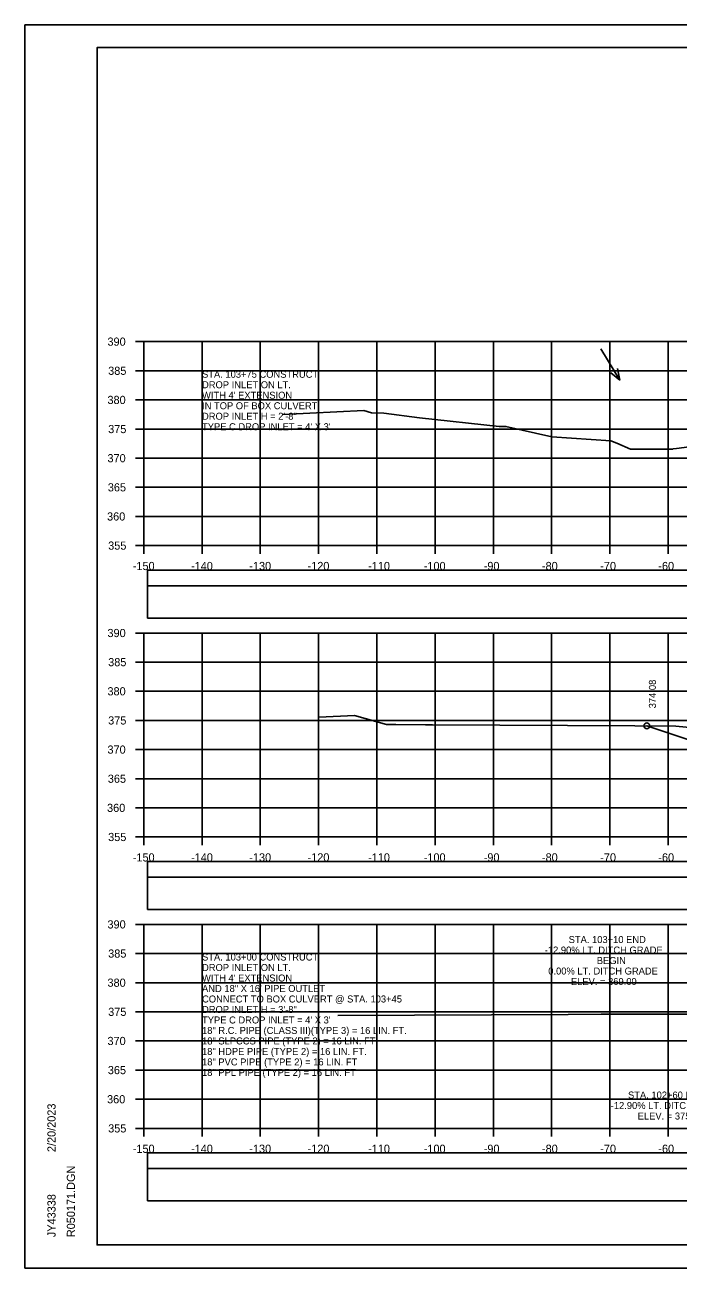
# Model space of a CAD drawing. Extents: x -37291014 to -37290680, y -936053 to -933067.
# Drawn here: x -37291013.5 to -37290901.4, y -935413.3 to -935200 of the extents above; entities that cross this region are included whole.
import ezdxf

# ---------------------------------------------------------------- set-up
doc = ezdxf.new("R2010")
doc.units = 0
for name, color, linetype in [('Default', 7, 'Continuous'), ('R_Axis', 7, 'Continuous'), ('R_Axis Annot', 7, 'Continuous'), ('R_Border', 7, 'Continuous'), ('R_Contours', 7, 'Continuous'), ('R_Exist Surface', 7, 'Continuous'), ('R_Fin Surface', 7, 'Continuous'), ('R_Grid', 7, 'Continuous'), ('R_No Plot', 7, 'Continuous'), ('R_Water Annot', 7, 'Continuous'), ('R_Xsect Elev', 7, 'Continuous')]:
    doc.layers.add(name, color=color, linetype=linetype)

msp = doc.modelspace()

# ---------------------------------------------------------------- linework, layer by layer
at = {"layer": 'Default'}
for points in [[(-37290992.48, -935296.22), (-37290693.72, -935296.22), (-37290693.72, -935293.51), (-37290992.48, -935293.51)], [(-37290992.48, -935301.74), (-37290693.72, -935301.74), (-37290693.72, -935296.22), (-37290992.48, -935296.22)], [(-37290992.48, -935346.22), (-37290693.72, -935346.22), (-37290693.72, -935343.51), (-37290992.48, -935343.51)], [(-37290992.48, -935351.74), (-37290693.72, -935351.74), (-37290693.72, -935346.22), (-37290992.48, -935346.22)], [(-37290992.48, -935396.22), (-37290693.72, -935396.22), (-37290693.72, -935393.51), (-37290992.48, -935393.51)], [(-37290992.48, -935401.74), (-37290693.72, -935401.74), (-37290693.72, -935396.22), (-37290992.48, -935396.22)]]:
    msp.add_lwpolyline(points, close=True, dxfattribs=at)
at = {"layer": 'R_Axis'}
for p, q in [((-37290994.5, -935254.31), (-37290993.1, -935254.31)), ((-37290993.1, -935289.31), (-37290993.1, -935254.31)), ((-37290994.5, -935259.31), (-37290993.1, -935259.31)), ((-37290994.5, -935264.31), (-37290993.1, -935264.31)), ((-37290994.5, -935269.31), (-37290993.1, -935269.31)), ((-37290994.5, -935274.31), (-37290993.1, -935274.31)), ((-37290994.5, -935279.31), (-37290993.1, -935279.31)), ((-37290994.5, -935284.31), (-37290993.1, -935284.31)), ((-37290994.5, -935289.31), (-37290993.1, -935289.31)), ((-37290993.1, -935289.31), (-37290693.1, -935289.31)), ((-37290993.1, -935290.71), (-37290993.1, -935289.31)), ((-37290983.1, -935290.71), (-37290983.1, -935289.31)), ((-37290973.1, -935290.71), (-37290973.1, -935289.31)), ((-37290963.1, -935290.71), (-37290963.1, -935289.31)), ((-37290953.1, -935290.71), (-37290953.1, -935289.31)), ((-37290943.1, -935290.71), (-37290943.1, -935289.31)), ((-37290933.1, -935290.71), (-37290933.1, -935289.31)), ((-37290923.1, -935290.71), (-37290923.1, -935289.31)), ((-37290913.1, -935290.71), (-37290913.1, -935289.31)), ((-37290903.1, -935290.71), (-37290903.1, -935289.31)), ((-37290994.5, -935304.31), (-37290993.1, -935304.31)), ((-37290993.1, -935339.31), (-37290993.1, -935304.31)), ((-37290994.5, -935309.31), (-37290993.1, -935309.31)), ((-37290994.5, -935314.31), (-37290993.1, -935314.31)), ((-37290994.5, -935319.31), (-37290993.1, -935319.31)), ((-37290994.5, -935324.31), (-37290993.1, -935324.31)), ((-37290994.5, -935329.31), (-37290993.1, -935329.31)), ((-37290994.5, -935334.31), (-37290993.1, -935334.31)), ((-37290994.5, -935339.31), (-37290993.1, -935339.31)), ((-37290993.1, -935339.31), (-37290693.1, -935339.31)), ((-37290993.1, -935340.71), (-37290993.1, -935339.31)), ((-37290983.1, -935340.71), (-37290983.1, -935339.31)), ((-37290973.1, -935340.71), (-37290973.1, -935339.31)), ((-37290963.1, -935340.71), (-37290963.1, -935339.31)), ((-37290953.1, -935340.71), (-37290953.1, -935339.31)), ((-37290943.1, -935340.71), (-37290943.1, -935339.31)), ((-37290933.1, -935340.71), (-37290933.1, -935339.31)), ((-37290923.1, -935340.71), (-37290923.1, -935339.31)), ((-37290913.1, -935340.71), (-37290913.1, -935339.31)), ((-37290903.1, -935340.71), (-37290903.1, -935339.31)), ((-37290994.5, -935354.31), (-37290993.1, -935354.31)), ((-37290993.1, -935389.31), (-37290993.1, -935354.31)), ((-37290994.5, -935359.31), (-37290993.1, -935359.31)), ((-37290994.5, -935364.31), (-37290993.1, -935364.31)), ((-37290994.5, -935369.31), (-37290993.1, -935369.31)), ((-37290994.5, -935374.31), (-37290993.1, -935374.31)), ((-37290994.5, -935379.31), (-37290993.1, -935379.31)), ((-37290994.5, -935384.31), (-37290993.1, -935384.31)), ((-37290994.5, -935389.31), (-37290993.1, -935389.31)), ((-37290993.1, -935389.31), (-37290693.1, -935389.31)), ((-37290993.1, -935390.71), (-37290993.1, -935389.31)), ((-37290983.1, -935390.71), (-37290983.1, -935389.31)), ((-37290973.1, -935390.71), (-37290973.1, -935389.31)), ((-37290963.1, -935390.71), (-37290963.1, -935389.31)), ((-37290953.1, -935390.71), (-37290953.1, -935389.31)), ((-37290943.1, -935390.71), (-37290943.1, -935389.31)), ((-37290933.1, -935390.71), (-37290933.1, -935389.31)), ((-37290923.1, -935390.71), (-37290923.1, -935389.31)), ((-37290913.1, -935390.71), (-37290913.1, -935389.31)), ((-37290903.1, -935390.71), (-37290903.1, -935389.31))]:
    msp.add_line(p, q, dxfattribs=at)
at = {"layer": 'R_Border'}
for p, q in [((-37291001.1, -935203.85), (-37290684.92, -935203.85)), ((-37291001.1, -935409.31), (-37291001.1, -935203.85)), ((-37291001.1, -935409.31), (-37291001.1, -935409.31)), ((-37290684.92, -935409.31), (-37291001.1, -935409.31))]:
    msp.add_line(p, q, dxfattribs=at)
at = {"layer": 'R_Contours'}
for points in [[(-37290883.54, -935322.53), (-37290886.6, -935321.98), (-37290887.07, -935321.81), (-37290896.49, -935320.81), (-37290901.79, -935320.28), (-37290906.76, -935320.23)], [(-37290906.76, -935320.23), (-37290891.52, -935325.31), (-37290883.3, -935322.57)]]:
    msp.add_lwpolyline(points, dxfattribs=at)
at = {"layer": 'R_Exist Surface'}
for points in [[(-37290969.25, -935266.79), (-37290955.32, -935266.15), (-37290954.01, -935266.51), (-37290951.92, -935266.59), (-37290945.77, -935267.37), (-37290932.12, -935268.87), (-37290930.96, -935268.85), (-37290923.05, -935270.62), (-37290912.93, -935271.35), (-37290911.92, -935271.75), (-37290909.54, -935272.77), (-37290907.92, -935272.77), (-37290902.28, -935272.74), (-37290902.23, -935272.73), (-37290901.68, -935272.65), (-37290897.77, -935272.12)], [(-37290962.98, -935318.74), (-37290956.91, -935318.47), (-37290951.43, -935319.98), (-37290949.84, -935320), (-37290944.77, -935320.04), (-37290943.53, -935320.04), (-37290908.82, -935320.21), (-37290901.79, -935320.28), (-37290896.49, -935320.81)], [(-37290959.82, -935369.94), (-37290920.28, -935369.77), (-37290914.61, -935369.74), (-37290913.95, -935369.74), (-37290875.06, -935369.72)]]:
    msp.add_lwpolyline(points, dxfattribs=at)
at = {"layer": 'R_Fin Surface'}
msp.add_lwpolyline([(-37290906.76, -935320.23), (-37290891.52, -935325.31)], dxfattribs=at)
at = {"layer": 'R_Grid'}
for p, q in [((-37290993.1, -935254.31), (-37290693.1, -935254.31)), ((-37290993.1, -935289.31), (-37290993.1, -935254.31)), ((-37290983.1, -935289.31), (-37290983.1, -935254.31)), ((-37290973.1, -935289.31), (-37290973.1, -935254.31)), ((-37290963.1, -935289.31), (-37290963.1, -935254.31)), ((-37290953.1, -935289.31), (-37290953.1, -935254.31)), ((-37290943.1, -935289.31), (-37290943.1, -935254.31)), ((-37290933.1, -935289.31), (-37290933.1, -935254.31)), ((-37290923.1, -935289.31), (-37290923.1, -935254.31)), ((-37290913.1, -935289.31), (-37290913.1, -935254.31)), ((-37290903.1, -935289.31), (-37290903.1, -935254.31)), ((-37290993.1, -935259.31), (-37290693.1, -935259.31)), ((-37290993.1, -935264.31), (-37290693.1, -935264.31)), ((-37290993.1, -935269.31), (-37290693.1, -935269.31)), ((-37290993.1, -935274.31), (-37290693.1, -935274.31)), ((-37290993.1, -935279.31), (-37290693.1, -935279.31)), ((-37290993.1, -935284.31), (-37290693.1, -935284.31)), ((-37290993.1, -935289.31), (-37290693.1, -935289.31)), ((-37290993.1, -935304.31), (-37290693.1, -935304.31)), ((-37290993.1, -935339.31), (-37290993.1, -935304.31)), ((-37290983.1, -935339.31), (-37290983.1, -935304.31)), ((-37290973.1, -935339.31), (-37290973.1, -935304.31)), ((-37290963.1, -935339.31), (-37290963.1, -935304.31)), ((-37290953.1, -935339.31), (-37290953.1, -935304.31)), ((-37290943.1, -935339.31), (-37290943.1, -935304.31)), ((-37290933.1, -935339.31), (-37290933.1, -935304.31)), ((-37290923.1, -935339.31), (-37290923.1, -935304.31)), ((-37290913.1, -935339.31), (-37290913.1, -935304.31)), ((-37290903.1, -935339.31), (-37290903.1, -935304.31)), ((-37290993.1, -935309.31), (-37290693.1, -935309.31)), ((-37290993.1, -935314.31), (-37290693.1, -935314.31)), ((-37290993.1, -935319.31), (-37290693.1, -935319.31)), ((-37290993.1, -935324.31), (-37290693.1, -935324.31)), ((-37290993.1, -935329.31), (-37290693.1, -935329.31)), ((-37290993.1, -935334.31), (-37290693.1, -935334.31)), ((-37290993.1, -935339.31), (-37290693.1, -935339.31)), ((-37290993.1, -935354.31), (-37290693.1, -935354.31)), ((-37290993.1, -935389.31), (-37290993.1, -935354.31)), ((-37290983.1, -935389.31), (-37290983.1, -935354.31)), ((-37290973.1, -935389.31), (-37290973.1, -935354.31)), ((-37290963.1, -935389.31), (-37290963.1, -935354.31)), ((-37290953.1, -935389.31), (-37290953.1, -935354.31)), ((-37290943.1, -935389.31), (-37290943.1, -935354.31)), ((-37290933.1, -935389.31), (-37290933.1, -935354.31)), ((-37290923.1, -935389.31), (-37290923.1, -935354.31)), ((-37290913.1, -935389.31), (-37290913.1, -935354.31)), ((-37290903.1, -935389.31), (-37290903.1, -935354.31)), ((-37290993.1, -935359.31), (-37290693.1, -935359.31)), ((-37290993.1, -935364.31), (-37290693.1, -935364.31)), ((-37290993.1, -935369.31), (-37290693.1, -935369.31)), ((-37290993.1, -935374.31), (-37290693.1, -935374.31)), ((-37290993.1, -935379.31), (-37290693.1, -935379.31)), ((-37290993.1, -935384.31), (-37290693.1, -935384.31)), ((-37290993.1, -935389.31), (-37290693.1, -935389.31))]:
    msp.add_line(p, q, dxfattribs=at)
at = {"layer": 'R_No Plot'}
for p, q in [((-37291013.5, -935199.96), (-37290680.17, -935199.96)), ((-37291013.5, -935413.29), (-37290680.17, -935413.29))]:
    msp.add_line(p, q, dxfattribs=at)
for points in [[(-37291013.51, -935199.96), (-37290680.17, -935199.96), (-37290680.17, -935413.29), (-37291013.51, -935413.29)], [(-37290767.18, -935203.85), (-37290747.56, -935203.85), (-37290747.56, -935213.73), (-37290731.45, -935213.73), (-37290708.25, -935213.73), (-37290708.25, -935238.06), (-37290684.92, -935238.06), (-37290684.92, -935409.31), (-37291001.1, -935409.31), (-37291001.1, -935203.85)]]:
    msp.add_lwpolyline(points, close=True, dxfattribs=at)
msp.add_circle((-37290906.76, -935320.23), 0.5, dxfattribs=at)
at = {"layer": 'R_Water Annot'}
for p, q in [((-37290914.65, -935255.55), (-37290911.37, -935260.92)), ((-37290911.37, -935260.92), (-37290912.97, -935259.64)), ((-37290911.37, -935260.92), (-37290911.78, -935258.91))]:
    msp.add_line(p, q, dxfattribs=at)

# ---------------------------------------------------------------- texts
at = {"layer": 'R_Axis Annot'}
for s, p in [('390', (-37290999.33, -935255.01)), ('385', (-37290999.21, -935260.01)), ('380', (-37290999.33, -935265.01)), ('375', (-37290999.21, -935270.01)), ('370', (-37290999.33, -935275.01)), ('365', (-37290999.27, -935280.01)), ('360', (-37290999.4, -935285.01)), ('355', (-37290999.21, -935290.01)), ('-150', (-37290994.99, -935293.51)), ('-140', (-37290984.99, -935293.51)), ('-130', (-37290974.99, -935293.51)), ('-120', (-37290964.99, -935293.51)), ('-110', (-37290954.6, -935293.51)), ('-100', (-37290945.05, -935293.51)), ('-90', (-37290934.76, -935293.51)), ('-80', (-37290924.76, -935293.51)), ('-70', (-37290914.76, -935293.51)), ('-60', (-37290904.79, -935293.51)), ('390', (-37290999.33, -935305.01)), ('385', (-37290999.21, -935310.01)), ('380', (-37290999.33, -935315.01)), ('375', (-37290999.21, -935320.01)), ('370', (-37290999.33, -935325.01)), ('365', (-37290999.27, -935330.01)), ('360', (-37290999.4, -935335.01)), ('355', (-37290999.21, -935340.01)), ('-150', (-37290994.99, -935343.51)), ('-140', (-37290984.99, -935343.51)), ('-130', (-37290974.99, -935343.51)), ('-120', (-37290964.99, -935343.51)), ('-110', (-37290954.6, -935343.51)), ('-100', (-37290945.05, -935343.51)), ('-90', (-37290934.76, -935343.51)), ('-80', (-37290924.76, -935343.51)), ('-70', (-37290914.76, -935343.51)), ('-60', (-37290904.79, -935343.51)), ('390', (-37290999.33, -935355.01)), ('385', (-37290999.21, -935360.01)), ('380', (-37290999.33, -935365.01)), ('375', (-37290999.21, -935370.01)), ('370', (-37290999.33, -935375.01)), ('365', (-37290999.27, -935380.01)), ('360', (-37290999.4, -935385.01)), ('355', (-37290999.21, -935390.01)), ('-150', (-37290994.99, -935393.51)), ('-140', (-37290984.99, -935393.51)), ('-130', (-37290974.99, -935393.51)), ('-120', (-37290964.99, -935393.51)), ('-110', (-37290954.6, -935393.51)), ('-100', (-37290945.05, -935393.51)), ('-90', (-37290934.76, -935393.51)), ('-80', (-37290924.76, -935393.51)), ('-70', (-37290914.76, -935393.51)), ('-60', (-37290904.79, -935393.51))]:
    msp.add_text(s, height=1.4, dxfattribs=at).set_placement(p)
at = {"layer": 'R_Border'}
for s, p in [('2/20/2023', (-37291008.24, -935393.38)), ('R050171.DGN', (-37291004.91, -935407.98)), ('JY43338', (-37291008.24, -935407.98))]:
    msp.add_text(s, height=1.4, rotation=90, dxfattribs=at).set_placement(p)
at = {"layer": 'R_Water Annot'}
for s, p in [('STA. 103+75 CONSTRUCT', (-37290983.1, -935260.51)), ('DROP INLET ON LT.', (-37290983.1, -935262.31)), ("WITH 4' EXTENSION", (-37290983.1, -935264.11)), ('IN TOP OF BOX CULVERT', (-37290983.1, -935265.91)), ('DROP INLET H = 2\'-8"', (-37290983.1, -935267.71)), ("TYPE C DROP INLET = 4' X 3'", (-37290983.1, -935269.51)), ('STA. 103+00 CONSTRUCT', (-37290983.1, -935360.51)), ('DROP INLET ON LT.', (-37290983.1, -935362.31)), ("WITH 4' EXTENSION", (-37290983.1, -935364.11)), ('AND 18" X 16\' PIPE OUTLET', (-37290983.1, -935365.91)), ('CONNECT TO BOX CULVERT @ STA. 103+45', (-37290983.1, -935367.71)), ('DROP INLET H = 3\'-8"', (-37290983.1, -935369.51)), ("TYPE C DROP INLET = 4' X 3'", (-37290983.1, -935371.31)), ('18" R.C. PIPE (CLASS III)(TYPE 3) = 16 LIN. FT.', (-37290983.1, -935373.11)), ('18" SLPCCS PIPE (TYPE 2) = 16 LIN. FT.', (-37290983.1, -935374.91)), ('18" HDPE PIPE (TYPE 2) = 16 LIN. FT.', (-37290983.1, -935376.71)), ('18" PVC PIPE (TYPE 2) = 16 LIN. FT', (-37290983.1, -935378.51)), ('18" PPL PIPE (TYPE 2) = 16 LIN. FT', (-37290983.1, -935380.31))]:
    msp.add_text(s, height=1.2, dxfattribs=at).set_placement(p)
at = {"layer": 'R_Xsect Elev'}
msp.add_text('374.08', height=1.2, rotation=90, dxfattribs=at).set_placement((-37290905.21, -935317.23))
for s, p in [('STA. 103+10 END', (-37290920.18, -935357.51)), ('-12.90% LT. DITCH GRADE', (-37290924.28, -935359.31)), ('BEGIN', (-37290915.35, -935361.11)), ('0.00% LT. DITCH GRADE', (-37290923.68, -935362.91)), ('ELEV. = 369.00', (-37290919.79, -935364.71)), ('STA. 102+60 BEGIN ', (-37290909.99, -935384.19)), ('-12.90% LT. DITCH GRADE', (-37290912.96, -935385.99)), ('ELEV. = 375.45', (-37290908.33, -935387.79))]:
    msp.add_text(s, height=1.2, dxfattribs=at).set_placement(p)

doc.saveas('drawing.dxf')
